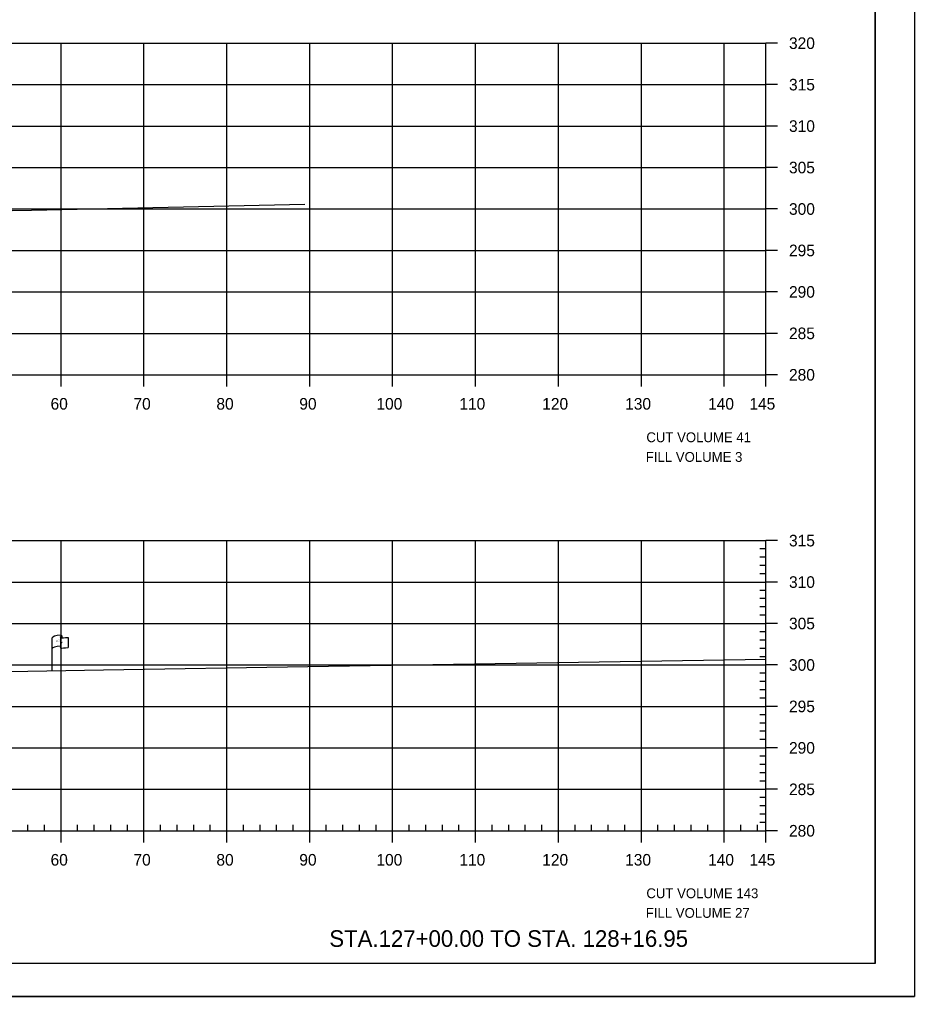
# Model space of a CAD drawing. Extents: x 1370843 to 1371177, y 380307 to 382654.
# Drawn here: x 1371068.7 to 1371176.6, y 382440.8 to 382558.7 of the extents above; entities that cross this region are included whole.
import ezdxf

# ---------------------------------------------------------------- set-up
doc = ezdxf.new("R2010")
doc.units = 0
for name, color, linetype in [('R_Axis', 7, 'Continuous'), ('R_Axis Annot', 7, 'Continuous'), ('R_Border', 7, 'Continuous'), ('R_Border Notes', 7, 'Continuous'), ('R_Draft', 7, 'Continuous'), ('R_Exist Surface', 7, 'Continuous'), ('R_Grid', 7, 'Continuous'), ('R_No Plot', 7, 'Continuous'), ('R_ROW', 7, 'Continuous')]:
    doc.layers.add(name, color=color, linetype=linetype)

msp = doc.modelspace()

# ---------------------------------------------------------------- linework, layer by layer
at = {"layer": 'R_Axis'}
for p, q in [((1371158.71, 382515.83), (1371158.71, 382555.83)), ((1371160.11, 382555.83), (1371158.71, 382555.83)), ((1371160.11, 382550.83), (1371158.71, 382550.83)), ((1371160.11, 382545.83), (1371158.71, 382545.83)), ((1371160.11, 382540.83), (1371158.71, 382540.83)), ((1371160.11, 382535.83), (1371158.71, 382535.83)), ((1371160.11, 382530.83), (1371158.71, 382530.83)), ((1371160.11, 382525.83), (1371158.71, 382525.83)), ((1371160.11, 382520.83), (1371158.71, 382520.83)), ((1370868.71, 382515.83), (1371158.71, 382515.83)), ((1371073.71, 382514.43), (1371073.71, 382515.83)), ((1371083.71, 382514.43), (1371083.71, 382515.83)), ((1371093.71, 382514.43), (1371093.71, 382515.83)), ((1371103.71, 382514.43), (1371103.71, 382515.83)), ((1371113.71, 382514.43), (1371113.71, 382515.83)), ((1371123.71, 382514.43), (1371123.71, 382515.83)), ((1371133.71, 382514.43), (1371133.71, 382515.83)), ((1371143.71, 382514.43), (1371143.71, 382515.83)), ((1371153.71, 382514.43), (1371153.71, 382515.83)), ((1371158.71, 382514.43), (1371158.71, 382515.83)), ((1371160.11, 382515.83), (1371158.71, 382515.83)), ((1371158.71, 382494.83), (1371158.01, 382494.83)), ((1371158.71, 382460.83), (1371158.71, 382495.83)), ((1371160.11, 382495.83), (1371158.71, 382495.83)), ((1371158.71, 382493.83), (1371158.01, 382493.83)), ((1371158.71, 382492.83), (1371158.01, 382492.83)), ((1371158.71, 382491.83), (1371158.01, 382491.83)), ((1371160.11, 382490.83), (1371158.71, 382490.83)), ((1371158.71, 382489.83), (1371158.01, 382489.83)), ((1371158.71, 382488.83), (1371158.01, 382488.83)), ((1371158.71, 382487.83), (1371158.01, 382487.83)), ((1371158.71, 382486.83), (1371158.01, 382486.83)), ((1371160.11, 382485.83), (1371158.71, 382485.83)), ((1371158.71, 382484.83), (1371158.01, 382484.83)), ((1371158.71, 382483.83), (1371158.01, 382483.83)), ((1371158.71, 382482.83), (1371158.01, 382482.83)), ((1371158.71, 382481.83), (1371158.01, 382481.83)), ((1371160.11, 382480.83), (1371158.71, 382480.83)), ((1371158.71, 382479.83), (1371158.01, 382479.83)), ((1371158.71, 382478.83), (1371158.01, 382478.83)), ((1371158.71, 382477.83), (1371158.01, 382477.83)), ((1371158.71, 382476.83), (1371158.01, 382476.83)), ((1371158.71, 382474.83), (1371158.01, 382474.83)), ((1371160.11, 382475.83), (1371158.71, 382475.83)), ((1371158.71, 382473.83), (1371158.01, 382473.83)), ((1371158.71, 382472.83), (1371158.01, 382472.83)), ((1371158.71, 382471.83), (1371158.01, 382471.83)), ((1371160.11, 382470.83), (1371158.71, 382470.83)), ((1371158.71, 382469.83), (1371158.01, 382469.83)), ((1371158.71, 382468.83), (1371158.01, 382468.83)), ((1371158.71, 382467.83), (1371158.01, 382467.83)), ((1371158.71, 382466.83), (1371158.01, 382466.83)), ((1371160.11, 382465.83), (1371158.71, 382465.83)), ((1371158.71, 382464.83), (1371158.01, 382464.83)), ((1371158.71, 382463.83), (1371158.01, 382463.83)), ((1371158.71, 382462.83), (1371158.01, 382462.83)), ((1371158.71, 382461.83), (1371158.01, 382461.83)), ((1370868.71, 382460.83), (1371158.71, 382460.83)), ((1371069.71, 382460.83), (1371069.71, 382461.53)), ((1371071.71, 382460.83), (1371071.71, 382461.53)), ((1371073.71, 382459.43), (1371073.71, 382460.83)), ((1371075.71, 382460.83), (1371075.71, 382461.53)), ((1371077.71, 382460.83), (1371077.71, 382461.53)), ((1371079.71, 382460.83), (1371079.71, 382461.53)), ((1371081.71, 382460.83), (1371081.71, 382461.53)), ((1371083.71, 382459.43), (1371083.71, 382460.83)), ((1371085.71, 382460.83), (1371085.71, 382461.53)), ((1371087.71, 382460.83), (1371087.71, 382461.53)), ((1371089.71, 382460.83), (1371089.71, 382461.53)), ((1371091.71, 382460.83), (1371091.71, 382461.53)), ((1371093.71, 382459.43), (1371093.71, 382460.83)), ((1371095.71, 382460.83), (1371095.71, 382461.53)), ((1371097.71, 382460.83), (1371097.71, 382461.53)), ((1371099.71, 382460.83), (1371099.71, 382461.53)), ((1371101.71, 382460.83), (1371101.71, 382461.53)), ((1371103.71, 382459.43), (1371103.71, 382460.83)), ((1371105.71, 382460.83), (1371105.71, 382461.53)), ((1371107.71, 382460.83), (1371107.71, 382461.53)), ((1371109.71, 382460.83), (1371109.71, 382461.53)), ((1371111.71, 382460.83), (1371111.71, 382461.53)), ((1371113.71, 382459.43), (1371113.71, 382460.83)), ((1371115.71, 382460.83), (1371115.71, 382461.53)), ((1371117.71, 382460.83), (1371117.71, 382461.53)), ((1371119.71, 382460.83), (1371119.71, 382461.53)), ((1371121.71, 382460.83), (1371121.71, 382461.53)), ((1371123.71, 382459.43), (1371123.71, 382460.83)), ((1371125.71, 382460.83), (1371125.71, 382461.53)), ((1371127.71, 382460.83), (1371127.71, 382461.53)), ((1371129.71, 382460.83), (1371129.71, 382461.53)), ((1371131.71, 382460.83), (1371131.71, 382461.53)), ((1371133.71, 382459.43), (1371133.71, 382460.83)), ((1371135.71, 382460.83), (1371135.71, 382461.53)), ((1371137.71, 382460.83), (1371137.71, 382461.53)), ((1371139.71, 382460.83), (1371139.71, 382461.53)), ((1371141.71, 382460.83), (1371141.71, 382461.53)), ((1371143.71, 382459.43), (1371143.71, 382460.83)), ((1371145.71, 382460.83), (1371145.71, 382461.53)), ((1371147.71, 382460.83), (1371147.71, 382461.53)), ((1371149.71, 382460.83), (1371149.71, 382461.53)), ((1371151.71, 382460.83), (1371151.71, 382461.53)), ((1371153.71, 382459.43), (1371153.71, 382460.83)), ((1371155.71, 382460.83), (1371155.71, 382461.53)), ((1371157.71, 382460.83), (1371157.71, 382461.53)), ((1371158.71, 382459.43), (1371158.71, 382460.83)), ((1371160.11, 382460.83), (1371158.71, 382460.83))]:
    msp.add_line(p, q, dxfattribs=at)
at = {"layer": 'R_Border'}
for q in [(1371171.89, 382650.29), (1370855.71, 382444.83)]:
    msp.add_line((1371171.89, 382444.83), q, dxfattribs=at)
at = {"layer": 'R_Exist Surface'}
msp.add_line((1371103.47, 382480.65), (1371158.71, 382481.54), dxfattribs=at)
for points in [[(1371053.83, 382535.42), (1371070.15, 382535.69), (1371103.12, 382536.41)], [(1371053.73, 382479.82), (1371078.82, 382480.25), (1371103.47, 382480.65)]]:
    msp.add_lwpolyline(points, dxfattribs=at)
at = {"layer": 'R_Grid'}
for p, q in [((1370868.71, 382555.83), (1371158.71, 382555.83)), ((1371073.71, 382515.83), (1371073.71, 382555.83)), ((1371083.71, 382515.83), (1371083.71, 382555.83)), ((1371093.71, 382515.83), (1371093.71, 382555.83)), ((1371103.71, 382515.83), (1371103.71, 382555.83)), ((1371113.71, 382515.83), (1371113.71, 382555.83)), ((1371123.71, 382515.83), (1371123.71, 382555.83)), ((1371133.71, 382515.83), (1371133.71, 382555.83)), ((1371143.71, 382515.83), (1371143.71, 382555.83)), ((1371153.71, 382515.83), (1371153.71, 382555.83)), ((1371158.71, 382515.83), (1371158.71, 382555.83)), ((1370868.71, 382550.83), (1371158.71, 382550.83)), ((1370868.71, 382545.83), (1371158.71, 382545.83)), ((1370868.71, 382540.83), (1371158.71, 382540.83)), ((1370868.71, 382535.83), (1371158.71, 382535.83)), ((1370868.71, 382530.83), (1371158.71, 382530.83)), ((1370868.71, 382525.83), (1371158.71, 382525.83)), ((1370868.71, 382520.83), (1371158.71, 382520.83)), ((1370868.71, 382515.83), (1371158.71, 382515.83)), ((1370868.71, 382495.83), (1371158.71, 382495.83)), ((1371073.71, 382460.83), (1371073.71, 382495.83)), ((1371083.71, 382460.83), (1371083.71, 382495.83)), ((1371093.71, 382460.83), (1371093.71, 382495.83)), ((1371103.71, 382460.83), (1371103.71, 382495.83)), ((1371113.71, 382460.83), (1371113.71, 382495.83)), ((1371123.71, 382460.83), (1371123.71, 382495.83)), ((1371133.71, 382460.83), (1371133.71, 382495.83)), ((1371143.71, 382460.83), (1371143.71, 382495.83)), ((1371153.71, 382460.83), (1371153.71, 382495.83)), ((1371158.71, 382460.83), (1371158.71, 382495.83)), ((1370868.71, 382490.83), (1371158.71, 382490.83)), ((1370868.71, 382485.83), (1371158.71, 382485.83)), ((1370868.71, 382480.83), (1371158.71, 382480.83)), ((1370868.71, 382475.83), (1371158.71, 382475.83)), ((1370868.71, 382470.83), (1371158.71, 382470.83)), ((1370868.71, 382465.83), (1371158.71, 382465.83)), ((1370868.71, 382460.83), (1371158.71, 382460.83))]:
    msp.add_line(p, q, dxfattribs=at)
at = {"layer": 'R_No Plot'}
msp.add_line((1370843.31, 382440.85), (1371176.64, 382440.85), dxfattribs=at)
for points in [[(1370843.3, 382654.18), (1371176.64, 382654.18), (1371176.64, 382440.85), (1370843.3, 382440.85)], [(1371089.63, 382650.29), (1371089.63, 382640.41), (1371125.36, 382640.41), (1371125.36, 382637.49), (1371148.56, 382637.49), (1371148.56, 382613.16), (1371171.89, 382613.16), (1371171.89, 382444.83), (1370855.71, 382444.83), (1370855.71, 382650.29)]]:
    msp.add_lwpolyline(points, close=True, dxfattribs=at)
at = {"layer": 'R_ROW'}
for p, q in [((1371073.63, 382484.19), (1371073.63, 382484.18)), ((1371073.63, 382484.18), (1371073.63, 382482.95)), ((1371073.79, 382484.35), (1371073.79, 382484.11)), ((1371072.63, 382480.15), (1371072.63, 382484.1)), ((1371074.56, 382484.16), (1371074.56, 382482.92))]:
    msp.add_line(p, q, dxfattribs=at)
for centre, radius, start, end in [((1371073.7, 382484.19), 0.078, 88.6458, 274.2828), ((1371073.72, 382484.35), 0.0783, 263.0712, 93.9564), ((1371073.7, 382482.95), 0.0783, 180, 273.9564)]:
    msp.add_arc(centre, radius, start, end, dxfattribs=at)
for centre, major_axis, ratio, start_param, end_param in [((1371074.21, 382484.14), (-1.58, -0.04), 0.19887, 5.030368, 6.283185), ((1371074.21, 382482.82), (-1.58, -0.04), 0.19887, 5.083035, 6.194897), ((1371074.92, 382484.26), (-1.23, -0.13), 0.052933, 0.159456, 1.268315), ((1371074.92, 382483.02), (-1.23, -0.13), 0.052933, 0.159456, 1.268315)]:
    msp.add_ellipse(centre, major_axis=major_axis, ratio=ratio, start_param=start_param, end_param=end_param, dxfattribs=at)

# ---------------------------------------------------------------- texts
at = {"layer": 'R_Axis Annot'}
for s, p in [('320', (1371161.51, 382555.13)), ('315', (1371161.51, 382550.13)), ('310', (1371161.51, 382545.13)), ('305', (1371161.51, 382540.13)), ('300', (1371161.51, 382535.13)), ('295', (1371161.51, 382530.13)), ('290', (1371161.51, 382525.13)), ('285', (1371161.51, 382520.13)), ('280', (1371161.51, 382515.13)), ('60', (1371072.45, 382511.63)), ('70', (1371082.45, 382511.63)), ('80', (1371092.45, 382511.63)), ('90', (1371102.45, 382511.63)), ('100', (1371111.75, 382511.63)), ('110', (1371121.75, 382511.63)), ('120', (1371131.75, 382511.63)), ('130', (1371141.75, 382511.63)), ('140', (1371151.75, 382511.63)), ('145', (1371156.73, 382511.63)), ('315', (1371161.51, 382495.13)), ('310', (1371161.51, 382490.13)), ('305', (1371161.51, 382485.13)), ('300', (1371161.51, 382480.13)), ('295', (1371161.51, 382475.13)), ('290', (1371161.51, 382470.13)), ('285', (1371161.51, 382465.13)), ('280', (1371161.51, 382460.13)), ('60', (1371072.45, 382456.63)), ('70', (1371082.45, 382456.63)), ('80', (1371092.45, 382456.63)), ('90', (1371102.45, 382456.63)), ('100', (1371111.75, 382456.63)), ('110', (1371121.75, 382456.63)), ('120', (1371131.75, 382456.63)), ('130', (1371141.75, 382456.63)), ('140', (1371151.75, 382456.63)), ('145', (1371156.73, 382456.63))]:
    msp.add_text(s, height=1.4, dxfattribs=at).set_placement(p)
at = {"layer": 'R_Border Notes'}
for s, p in [('CUT VOLUME 41', (1371144.31, 382507.7)), ('FILL VOLUME 3', (1371144.24, 382505.33)), ('CUT VOLUME 143', (1371144.31, 382452.7)), ('FILL VOLUME 27', (1371144.24, 382450.33))]:
    msp.add_text(s, height=1.1875, dxfattribs=at).set_placement(p)
at = {"layer": 'R_Draft'}
msp.add_text('STA.127+00.00 TO STA. 128+16.95', height=2, dxfattribs=at).set_placement((1371106.07, 382446.83))
at = {"layer": 'R_ROW'}
for s, height, rotation, p in [('R ', 0.2, 9.9884, (1371073.15, 382483.6)), (' O', 0.2, 9.9884, (1371073.3, 382483.64)), ('W', 0.2, 351.1788, (1371073.63, 382483.48)), ('DWB 11-9-07', 0.001, 90, (1371073.79, 382484.11)), ('DWB 11-9-07', 0.001, 5.0717, (1371074.55, 382482.91)), ('DWB 11-9-07', 0.001, 90, (1371072.63, 382480.15))]:
    msp.add_text(s, height=height, rotation=rotation, dxfattribs=at).set_placement(p)

doc.saveas('drawing.dxf')
